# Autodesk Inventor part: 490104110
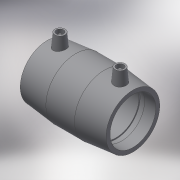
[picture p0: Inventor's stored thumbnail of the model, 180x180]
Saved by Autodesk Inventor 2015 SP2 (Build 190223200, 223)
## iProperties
Created: 2017-06
Part Number: 490104110
Material: Generic
Description: PLASSON COUPLER 110-110
Document SubType Name: Modeling
Designer: KIM
Mass: 634.769 g
Surface Area: 1350.44 cm^2
Volume: 634.769 cm^3
Density: 1 g/cm^3
Appearance: Default
Author: KIM
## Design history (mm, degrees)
derived "490104.ipt"
feature "Solid1::490104.ipt"
tag "TaggingFeature1"
body "Solid1"
other parameters: "d0" = 163, "d2" = 135, "d4" = 54.33333, "d5" = 121.5, "d6" = 104.5, "d8" = 168 deg, "d10" = 32, "d11" = 10.66667, "d13" = 163, "d14" = 17.6296, "d17" = 104.5, "d19" = 3.52592, "d20" = 168 deg, "d22" = 126.9, "d23" = 135, "d24" = 123.093, "d25" = 135 deg, "d26" = 65.2, "d27" = 135 deg, "d29" = 81, "d30" = 14, "d31" = 57.05, "d34" = 5 deg, "d35" = 15, "d39" = 5 deg, "d41" = 4, "d42" = 14, "d43" = 0, "d45" = 4, "d46" = 14, "d47" = 0, "d48" = 3, "d49" = 0, "d50" = 3, "d51" = 0, "d52" = 23.2, "d53" = 5.8, "L_" = 163, "D_" = 135, "A_" = 81, "d_2" = 12
